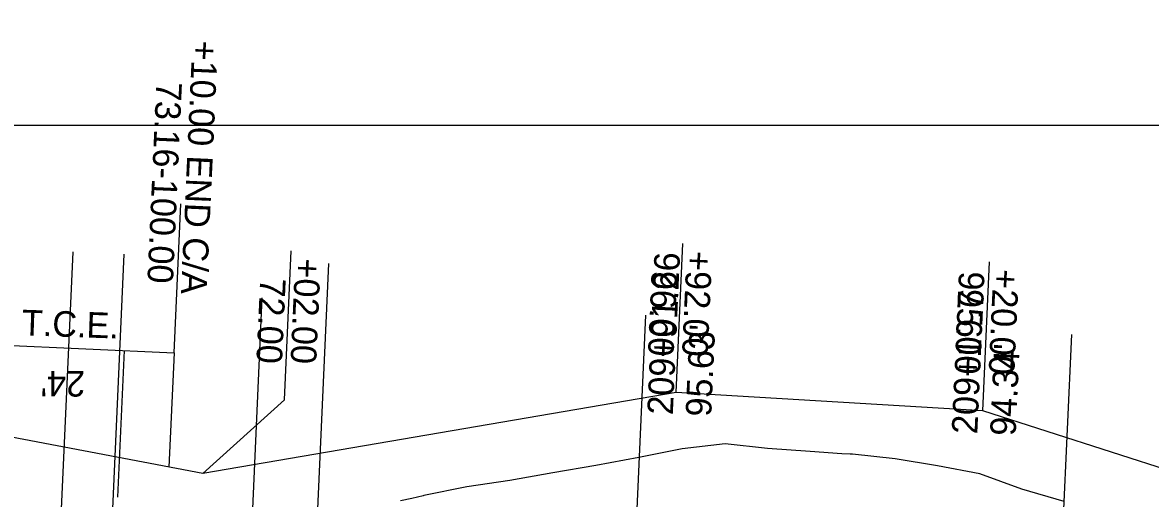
# Model space of a CAD drawing. Extents: x -70 to 701944, y -4 to 666871.
# Drawn here: x 667051.7 to 667316.2, y 656654.4 to 656766 of the extents above; entities that cross this region are included whole.
import ezdxf

# ---------------------------------------------------------------- set-up
doc = ezdxf.new("R2010")
doc.units = 0
for name, color, linetype in [('R_Detour', 7, 'Continuous'), ('R_Draft', 7, 'Continuous'), ('R_Drive', 7, 'Continuous'), ('R_No Plot', 7, 'Continuous'), ('R_Proposed Const Limits', 7, 'Continuous'), ('R_ROW', 7, 'Continuous'), ('R_ROW Annot', 7, 'Continuous'), ('R_Temp Easement', 7, 'Continuous'), ('R_Temp Easement Annot', 7, 'Continuous')]:
    doc.layers.add(name, color=color, linetype=linetype)

msp = doc.modelspace()

# ---------------------------------------------------------------- linework, layer by layer
at = {"layer": 'R_Detour'}
for p, q in [((668023.64, 656741.87), (666796.56, 656741.87)), ((667107.85, 656701.47), (667102.71, 656587.75)), ((667197.76, 656697.4), (667192.62, 656583.69)), ((667297.66, 656692.89), (667292.52, 656579.17))]:
    msp.add_line(p, q, dxfattribs=at)
at = {"layer": 'R_Draft'}
for p, q in [((667052.91, 656475.92), (667063.59, 656712.25)), ((667064.9, 656475.37), (667075.58, 656711.7)), ((667112.85, 656473.21), (667123.53, 656709.54))]:
    msp.add_line(p, q, dxfattribs=at)
at = {"layer": 'R_Drive'}
msp.add_line((667075.56, 656689.08), (667074, 656654.67), dxfattribs=at)
at = {"layer": 'R_Proposed Const Limits'}
msp.add_lwpolyline([(667295.89, 656653.66), (667286.01, 656656.59), (667276.16, 656660.19), (667266.24, 656662.08), (667256.3, 656663.72), (667246.34, 656664.75), (667245.74, 656664.81), (667243.84, 656664.89), (667236.35, 656665.37), (667226.38, 656666.11), (667216.42, 656667.2), (667206.36, 656666.06), (667196.25, 656663.99), (667186.16, 656662.16), (667176.07, 656660.44), (667165.98, 656658.58), (667155.9, 656657.1), (667145.8, 656655.08), (667145.62, 656655.04), (667143, 656654.42), (667140.37, 656653.8)], dxfattribs=at)
at = {"layer": 'R_ROW'}
msp.add_lwpolyline([(668183.45, 656677.29), (668041.7, 656619.63), (667513.59, 656642.26), (667480, 656629.76), (667392.27, 656637.73), (667276.83, 656674.98), (667204.95, 656679.23), (667093.98, 656660.22), (667018.55, 656674.64), (666944.63, 656677.98), (666832.93, 656665.01), (666352.77, 656716.73), (665777.5, 656723.7), (665727.42, 656722.96), (665452.7, 656735.37), (665090.34, 656757.75), (665090.29, 656778.78), (664696.26, 656796.57), (664695.54, 656784.55), (664566.62, 656799.96)], dxfattribs=at)
at = {"layer": 'R_ROW Annot'}
for points in [[(667087.25, 656688.55), (667088.83, 656723.52)], [(667093.98, 656660.22), (667113.16, 656677.49), (667114.74, 656712.46)], [(667204.95, 656679.23), (667206.53, 656714.19)], [(667276.83, 656674.98), (667278.41, 656709.94)]]:
    msp.add_lwpolyline(points, dxfattribs=at)
at = {"layer": 'R_Temp Easement'}
for p, q in [((667037.3, 656690.81), (667087.25, 656688.55)), ((667087.25, 656688.55), (667086.04, 656661.74))]:
    msp.add_line(p, q, dxfattribs=at)

# ---------------------------------------------------------------- texts
at = {"layer": 'R_Drive'}
msp.add_text("24'", height=6, rotation=179.7886, dxfattribs=at).set_placement((667066.42, 656684.29))
at = {"layer": 'R_No Plot'}
for s, p in [('209+91.26 ', (667204.17, 656673.9)), ('209+19.76 ', (667275.55, 656669.38)), ("95.63' ", (667213.16, 656673.49)), ("94.34' ", (667284.54, 656668.98))]:
    msp.add_text(s, height=6, rotation=87.4131, dxfattribs=at).set_placement(p)
at = {"layer": 'R_ROW Annot'}
for s, p in [('+10.00 END C/A', (667091.56, 656761.91)), ('73.16-100.00', (667083.12, 656752.21)), ('+92.00', (667207.45, 656712.56)), ('+02.00', (667115.67, 656710.82)), ('96.00', (667199.24, 656707.92)), ('+20.00', (667279.34, 656708.31)), ('72.00', (667107.45, 656706.19)), ('95.00', (667271.12, 656703.68))]:
    msp.add_text(s, height=6, rotation=267.4131, dxfattribs=at).set_placement(p)
at = {"layer": 'R_Temp Easement Annot'}
msp.add_text('T.C.E.', height=6, rotation=358.0088, dxfattribs=at).set_placement((667051.49, 656692.68))

doc.saveas('drawing.dxf')
